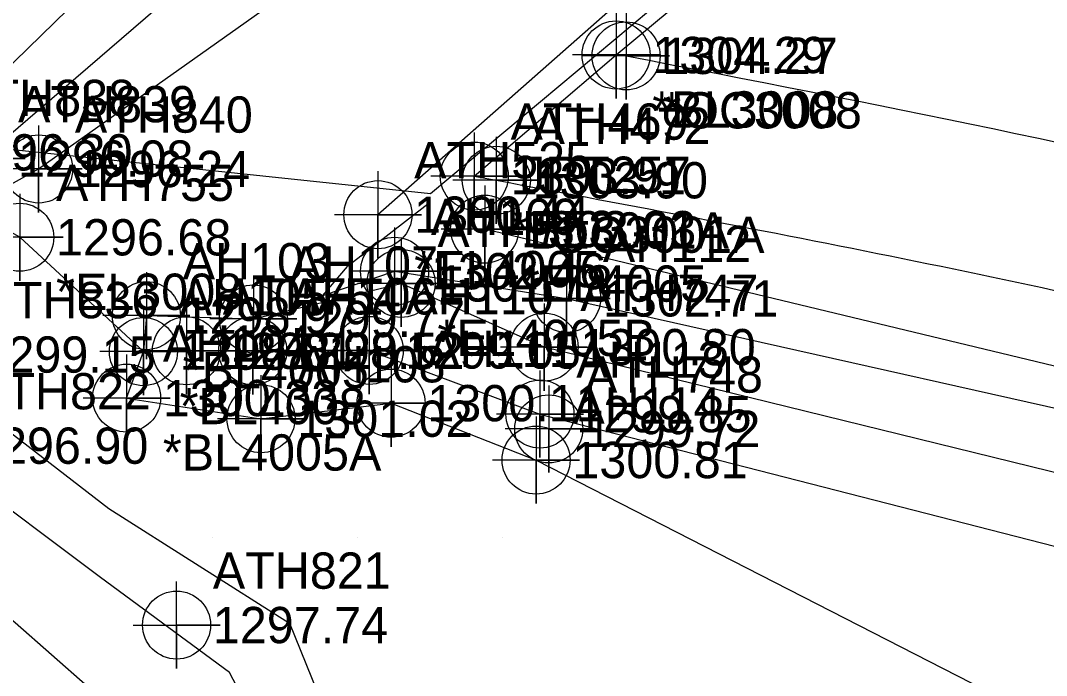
# Model space of a CAD drawing. Extents: x 1234484 to 1235382, y 695050 to 695510.
# Drawn here: x 1234936.8 to 1235007.5, y 695270.5 to 695315.6 of the extents above; entities that cross this region are included whole.
import ezdxf

# ---------------------------------------------------------------- set-up
doc = ezdxf.new("R2010")
doc.units = 0
for name, color, linetype in [('Exist DTM Breakline', 7, 'Continuous'), ('Exist DTM Breakline Cogo Comment', 7, 'Continuous'), ('Exist DTM Breakline Cogo Elevation', 7, 'Continuous'), ('Exist DTM Breakline Cogo Number', 7, 'Continuous'), ('Exist DTM Breakline Cogo Point CELL', 7, 'Continuous'), ('Exist DTM Breakline Underwater', 7, 'Continuous'), ('Exist DTM Crownline', 7, 'Continuous'), ('Exist DTM Crownline Cogo Comment', 7, 'Continuous'), ('Exist DTM Crownline Cogo Elevation', 7, 'Continuous'), ('Exist DTM Crownline Cogo Number', 7, 'Continuous'), ('Exist DTM Crownline Cogo Point CELL', 7, 'Continuous'), ('Exist DTM Drainline Cogo Elevation', 7, 'Continuous'), ('Exist DTM Drainline Cogo Number', 7, 'Continuous'), ('Exist DTM Drainline Cogo Point CELL', 7, 'Continuous'), ('Exist DTM QL2 LIDAR Elevation Point', 7, 'Continuous'), ('Exist DTM Regular Point Cogo Elevation', 7, 'Continuous'), ('Exist DTM Regular Point Cogo Number', 7, 'Continuous'), ('Exist DTM Regular Point Underwater CELL', 7, 'Continuous'), ('Exist DTM Regular Point Underwater Cogo Comment', 7, 'Continuous'), ('Exist DTM Regular Point Underwater Cogo Elevation', 7, 'Continuous'), ('Exist DTM Regular Point Underwater Cogo Number', 7, 'Continuous'), ('Exist Hydro Stream or Body of Water', 7, 'Continuous'), ('Exist Hydro Stream or Body of Water Cogo Elevation', 7, 'Continuous'), ('Exist Hydro Stream or Body of Water Cogo Number', 7, 'Continuous'), ('Exist Hydro Stream or Body of Water Cogo Point CELL', 7, 'Continuous'), ('Exist Roads EOP', 7, 'Continuous'), ('Exist Roads EOP Cogo Comment', 7, 'Continuous'), ('Exist Roads EOP Cogo Elevation', 7, 'Continuous'), ('Exist Roads EOP Cogo Number', 7, 'Continuous'), ('Exist Roads EOP Cogo Point CELL', 7, 'Continuous'), ('Exist Structure Major Deck Tunnel Box Culvert', 7, 'Continuous')]:
    doc.layers.add(name, color=color, linetype=linetype)

msp = doc.modelspace()

# ---------------------------------------------------------------- linework, layer by layer
at = {"layer": 'Exist DTM Breakline'}
for p, q in [((1234990.761, 695328.067), (1234961.429, 695302.218)), ((1234964.862, 695302.939), (1234959.346, 695298.638)), ((1234957.627, 695296.648), (1234959.346, 695298.638))]:
    msp.add_line(p, q, dxfattribs=at)
for points in [[(1235258.778, 695187.05), (1235221.35, 695207.416), (1235173.519, 695232.644), (1235125.211, 695254.804), (1235075.73, 695275.107), (1235023.735, 695288.012), (1234968.789, 695301.22)], [(1234957.627, 695296.648), (1234962.584, 695298.324), (1234974.436, 695296.452), (1235023.384, 695285.46)], [(1234933.683, 695295.436), (1234929.419, 695292.356), (1234942.895, 695281.98), (1234955.338, 695274.07), (1234960.662, 695260.925), (1234955.311, 695244.507), (1234951.042, 695246.761), (1234943.062, 695238.239), (1234919.786, 695222.886), (1234917.573, 695214.076), (1234899.933, 695199.243), (1234885.657, 695179.089)], [(1234882.128, 695182.331), (1234896.107, 695201.799), (1234912.336, 695216.249), (1234916.953, 695226.235), (1234940.483, 695242.348), (1234951.207, 695257.798), (1234946.446, 695265.278), (1234936.421, 695274.091), (1234919.314, 695287.826), (1234914.388, 695289.733)]]:
    msp.add_lwpolyline(points, dxfattribs=at)
at = {"layer": 'Exist DTM Breakline Cogo Point CELL'}
for points in [[(1234961.429, 695305.218), (1234961.429, 695299.218), (1234961.429, 695302.218), (1234964.429, 695302.218), (1234958.429, 695302.218)], [(1234968.789, 695304.22), (1234968.789, 695298.22), (1234968.789, 695301.22), (1234971.789, 695301.22), (1234965.789, 695301.22)], [(1234962.584, 695301.324), (1234962.584, 695295.324), (1234962.584, 695298.324), (1234965.584, 695298.324), (1234959.584, 695298.324)], [(1234963.03, 695300.482), (1234963.03, 695294.482), (1234963.03, 695297.482), (1234966.03, 695297.482), (1234960.03, 695297.482)], [(1234974.436, 695299.452), (1234974.436, 695293.452), (1234974.436, 695296.452), (1234977.436, 695296.452), (1234971.436, 695296.452)], [(1234945.477, 695298.262), (1234945.477, 695292.262), (1234945.477, 695295.262), (1234948.477, 695295.262), (1234942.477, 695295.262)], [(1234952.851, 695298.033), (1234952.851, 695292.033), (1234952.851, 695295.033), (1234955.851, 695295.033), (1234949.851, 695295.033)], [(1234972.886, 695296.093), (1234972.886, 695290.093), (1234972.886, 695293.093), (1234975.886, 695293.093), (1234969.886, 695293.093)], [(1234944.112, 695292.587), (1234944.112, 695286.587), (1234944.112, 695289.587), (1234947.112, 695289.587), (1234941.112, 695289.587)], [(1234962.335, 695292.234), (1234962.335, 695286.234), (1234962.335, 695289.234), (1234965.335, 695289.234), (1234959.335, 695289.234)], [(1234953.373, 695291.163), (1234953.373, 695285.163), (1234953.373, 695288.163), (1234956.373, 695288.163), (1234950.373, 695288.163)], [(1234972.332, 695288.316), (1234972.332, 695282.316), (1234972.332, 695285.316), (1234975.332, 695285.316), (1234969.332, 695285.316)]]:
    msp.add_lwpolyline(points, dxfattribs=at)
for centre in [(1234961.429, 695302.218), (1234968.789, 695301.22), (1234962.584, 695298.324), (1234963.03, 695297.482), (1234974.436, 695296.452), (1234945.477, 695295.262), (1234952.851, 695295.033), (1234972.886, 695293.093), (1234944.112, 695289.587), (1234962.335, 695289.234), (1234953.373, 695288.163), (1234972.332, 695285.316)]:
    msp.add_circle(centre, 2.344, dxfattribs=at)
at = {"layer": 'Exist DTM Breakline Underwater'}
for points in [[(1234766.421, 695209.389), (1234812.885, 695247.237), (1234843.411, 695272.621), (1234869.986, 695279.055), (1234895.378, 695289.036), (1234916.238, 695295.408), (1234934.131, 695306.081), (1234961.466, 695329.617), (1234991.436, 695342.664), (1235009.265, 695346.147), (1235040.352, 695365.623), (1235072.367, 695380.008), (1235092.174, 695396.335)], [(1234948.239, 695292.841), (1234952.805, 695292.84), (1234960.83, 695292.864), (1234972.599, 695288.481), (1235023.203, 695275.502), (1235056.399, 695264.585), (1235086.587, 695258.395), (1235121.582, 695234.941), (1235168.445, 695213.485), (1235191.313, 695204.186), (1235209.05, 695188.429), (1235246.922, 695166.749), (1235265.478, 695149.496)]]:
    msp.add_lwpolyline(points, dxfattribs=at)
at = {"layer": 'Exist DTM Crownline'}
msp.add_line((1234977.842, 695313.219), (1234978.534, 695313.159), dxfattribs=at)
msp.add_spline([(1234978.534, 695313.159), (1235028.867, 695302.317), (1235079.475, 695286.154), (1235130.202, 695265.942), (1235178.94, 695242.599), (1235226.8, 695217.474)], degree=3, dxfattribs=at)
at = {"layer": 'Exist DTM Crownline Cogo Point CELL'}
for points in [[(1234977.842, 695316.219), (1234977.842, 695310.219), (1234977.842, 695313.219), (1234980.842, 695313.219), (1234974.842, 695313.219)], [(1234978.534, 695316.159), (1234978.534, 695310.159), (1234978.534, 695313.159), (1234981.534, 695313.159), (1234975.534, 695313.159)], [(1234936.748, 695303.66), (1234936.748, 695297.66), (1234936.748, 695300.66), (1234939.748, 695300.66), (1234933.748, 695300.66)]]:
    msp.add_lwpolyline(points, dxfattribs=at)
for centre in [(1234977.842, 695313.219), (1234978.534, 695313.159), (1234936.748, 695300.66)]:
    msp.add_circle(centre, 2.344, dxfattribs=at)
at = {"layer": 'Exist DTM Drainline Cogo Point CELL'}
msp.add_lwpolyline([(1234938.044, 695308.366), (1234938.044, 695302.366), (1234938.044, 695305.366), (1234941.044, 695305.366), (1234935.044, 695305.366)], dxfattribs=at)
msp.add_circle((1234938.044, 695305.366), 2.344, dxfattribs=at)
at = {"layer": 'Exist DTM QL2 LIDAR Elevation Point'}
for p, q in [((1234950, 695280), (1234950, 695280)), ((1234960, 695280), (1234960, 695280)), ((1234970, 695280), (1234970, 695280))]:
    msp.add_line(p, q, dxfattribs=at)
at = {"layer": 'Exist DTM Regular Point Underwater CELL'}
for points in [[(1234934.131, 695309.081), (1234934.131, 695303.081), (1234934.131, 695306.081), (1234937.131, 695306.081), (1234931.131, 695306.081)], [(1234945.266, 695295.782), (1234945.266, 695289.782), (1234945.266, 695292.782), (1234948.266, 695292.782), (1234942.266, 695292.782)], [(1234948.239, 695295.841), (1234948.239, 695289.841), (1234948.239, 695292.841), (1234951.239, 695292.841), (1234945.239, 695292.841)], [(1234952.805, 695295.84), (1234952.805, 695289.84), (1234952.805, 695292.84), (1234955.805, 695292.84), (1234949.805, 695292.84)], [(1234960.83, 695295.864), (1234960.83, 695289.864), (1234960.83, 695292.864), (1234963.83, 695292.864), (1234957.83, 695292.864)], [(1234972.599, 695291.481), (1234972.599, 695285.481), (1234972.599, 695288.481), (1234975.599, 695288.481), (1234969.599, 695288.481)], [(1234973.204, 695290.456), (1234973.204, 695284.456), (1234973.204, 695287.456), (1234976.204, 695287.456), (1234970.204, 695287.456)]]:
    msp.add_lwpolyline(points, dxfattribs=at)
for centre in [(1234945.266, 695292.782), (1234948.239, 695292.841), (1234952.805, 695292.84), (1234960.83, 695292.864), (1234972.599, 695288.481), (1234973.204, 695287.456)]:
    msp.add_circle(centre, 2.344, dxfattribs=at)
at = {"layer": 'Exist Hydro Stream or Body of Water'}
for p, q in [((1234933.154, 695302.663), (1234938.044, 695305.366)), ((1234952.851, 695295.033), (1234963.03, 695297.482)), ((1234945.477, 695295.262), (1234945.266, 695292.782))]:
    msp.add_line(p, q, dxfattribs=at)
for points in [[(1234766.439, 695214.543), (1234809.451, 695250.146), (1234840.783, 695273.683), (1234870.231, 695281.467), (1234894.384, 695292.767), (1234915.014, 695298.345), (1234929.933, 695306.511), (1234953.845, 695329.807), (1234986.204, 695341.472), (1235008.526, 695348.915), (1235037.336, 695368.653), (1235069.491, 695383.302), (1235088.448, 695400.861)], [(1234938.044, 695305.366), (1234971.304, 695328.94), (1234992.169, 695338.626), (1235010.649, 695342.979), (1235043.523, 695362.073), (1235076.562, 695377.561), (1235094.01, 695394.044)], [(1234944.112, 695289.587), (1234945.266, 695292.782), (1234936.748, 695300.66), (1234933.154, 695302.663)], [(1235024.437, 695280.431), (1234972.886, 695293.093), (1234963.03, 695297.482)], [(1234945.477, 695295.262), (1234952.851, 695295.033)], [(1234884.024, 695180.655), (1234897.944, 695200.742), (1234915.887, 695215.628), (1234918.027, 695224.801), (1234941.893, 695240.452), (1234957.27, 695259.086), (1234951.207, 695270.685), (1234942.31, 695277.234), (1234922.587, 695292.008)], [(1234944.112, 695289.587), (1234953.373, 695288.163), (1234962.335, 695289.234), (1234972.332, 695285.316), (1235018.754, 695261.568)]]:
    msp.add_lwpolyline(points, dxfattribs=at)
at = {"layer": 'Exist Hydro Stream or Body of Water Cogo Point CELL'}
msp.add_lwpolyline([(1234944.554, 695273.948), (1234950.554, 695273.948), (1234947.554, 695273.948), (1234947.554, 695270.948), (1234947.554, 695276.948)], dxfattribs=at)
msp.add_circle((1234947.554, 695273.948), 2.344, dxfattribs=at)
at = {"layer": 'Exist Roads EOP'}
msp.add_line((1234968.075, 695304.88), (1234969.592, 695304.589), dxfattribs=at)
msp.add_lwpolyline([(1234968.075, 695304.88), (1234977.842, 695313.219), (1234987.73, 695321.443)], dxfattribs=at)
for points in [[(1234989.744, 695321.275), (1235032.632, 695310.758), (1235082.97, 695294.625), (1235134.247, 695274.482), (1235183.928, 695250.955), (1235232.115, 695225.68)], [(1234969.592, 695304.589), (1235025.451, 695292.964), (1235076.313, 695277.193), (1235126.218, 695256.569), (1235174.523, 695234.324), (1235222.247, 695208.988)]]:
    msp.add_spline(points, degree=3, dxfattribs=at)
at = {"layer": 'Exist Roads EOP Cogo Point CELL'}
for points in [[(1234968.075, 695307.88), (1234968.075, 695301.88), (1234968.075, 695304.88), (1234971.075, 695304.88), (1234965.075, 695304.88)], [(1234969.592, 695307.589), (1234969.592, 695301.589), (1234969.592, 695304.589), (1234972.592, 695304.589), (1234966.592, 695304.589)]]:
    msp.add_lwpolyline(points, dxfattribs=at)
for centre in [(1234968.075, 695304.88), (1234969.592, 695304.589)]:
    msp.add_circle(centre, 2.344, dxfattribs=at)
at = {"layer": 'Exist Structure Major Deck Tunnel Box Culvert'}
msp.add_lwpolyline([(1234932.242, 695330.836), (1234906.381, 695309.848), (1234965.045, 695303.686), (1234990.33, 695324.837), (1234932.242, 695330.836)], dxfattribs=at)

# ---------------------------------------------------------------- texts
at = {"layer": 'Exist DTM Breakline Cogo Comment'}
for s, p in [('*EL4005', (1234963.929, 695297.218)), ('*EL4005', (1234971.289, 695296.22)), ('*EL4005B', (1234965.53, 695292.482)), ('*BL4005', (1234947.977, 695290.262)), ('*BL4005A', (1234946.612, 695284.587))]:
    msp.add_text(s, height=2.5, dxfattribs=at).set_placement(p)
at = {"layer": 'Exist DTM Breakline Cogo Elevation'}
for s, p in [('1300.44', (1234963.929, 695300.968)), ('1303.33', (1234971.289, 695299.97)), ('1302.46', (1234965.084, 695297.074)), ('1301.78', (1234965.53, 695296.232)), ('1302.71', (1234976.936, 695295.202)), ('1298.97', (1234947.977, 695294.012)), ('1299.77', (1234955.351, 695293.783)), ('1300.80', (1234975.386, 695291.843)), ('1300.33', (1234946.612, 695288.337)), ('1300.11', (1234964.835, 695287.984)), ('1301.02', (1234955.873, 695286.913)), ('1300.81', (1234974.832, 695284.066))]:
    msp.add_text(s, height=2.5, dxfattribs=at).set_placement(p)
at = {"layer": 'Exist DTM Breakline Cogo Number'}
for s, p in [('ATH525', (1234963.929, 695304.718)), ('JRT257', (1234971.289, 695303.72)), ('AH109', (1234965.084, 695300.824)), ('ATH753', (1234965.53, 695299.982)), ('AH112', (1234976.936, 695298.952)), ('AH103', (1234947.977, 695297.762)), ('AH107', (1234955.351, 695297.533)), ('ATH747', (1234975.386, 695295.593)), ('AH104', (1234946.612, 695292.087)), ('AH111', (1234964.835, 695291.734)), ('AH108', (1234955.873, 695290.663)), ('AH114', (1234974.832, 695287.816))]:
    msp.add_text(s, height=2.5, dxfattribs=at).set_placement(p)
at = {"layer": 'Exist DTM Crownline Cogo Comment'}
for s, p in [('*BL3008', (1234980.342, 695308.219)), ('*OC3008', (1234981.034, 695308.159)), ('*EL3008', (1234939.248, 695295.66))]:
    msp.add_text(s, height=2.5, dxfattribs=at).set_placement(p)
at = {"layer": 'Exist DTM Crownline Cogo Elevation'}
for s, p in [('1304.29', (1234980.342, 695311.969)), ('1304.27', (1234981.034, 695311.909)), ('1296.68', (1234939.248, 695299.41))]:
    msp.add_text(s, height=2.5, dxfattribs=at).set_placement(p)
at = {"layer": 'Exist DTM Crownline Cogo Number'}
msp.add_text('ATH755', height=2.5, dxfattribs=at).set_placement((1234939.248, 695303.16))
at = {"layer": 'Exist DTM Drainline Cogo Elevation'}
for s, p in [('1296.30', (1234932.433, 695305.261)), ('1296.24', (1234940.544, 695304.116))]:
    msp.add_text(s, height=2.5, dxfattribs=at).set_placement(p)
at = {"layer": 'Exist DTM Drainline Cogo Number'}
for s, p in [('ATH838', (1234932.433, 695309.011)), ('ATH840', (1234940.544, 695307.866))]:
    msp.add_text(s, height=2.5, dxfattribs=at).set_placement(p)
at = {"layer": 'Exist DTM Regular Point Cogo Elevation'}
msp.add_text('1299.15', height=2.5, dxfattribs=at).set_placement((1234934.035, 695291.334))
at = {"layer": 'Exist DTM Regular Point Cogo Number'}
msp.add_text('ATH836', height=2.5, dxfattribs=at).set_placement((1234934.035, 695295.084))
at = {"layer": 'Exist DTM Regular Point Underwater Cogo Comment'}
msp.add_text('*BL4008', height=2.5, dxfattribs=at).set_placement((1234947.766, 695287.782))
at = {"layer": 'Exist DTM Regular Point Underwater Cogo Elevation'}
for s, p in [('1296.08', (1234936.631, 695304.831)), ('1298.01', (1234947.766, 695291.532)), ('1298.29', (1234950.739, 695291.591)), ('1298.52', (1234955.305, 695291.59)), ('1299.05', (1234963.33, 695291.614)), ('1299.85', (1234975.099, 695287.231)), ('1299.72', (1234975.704, 695286.206))]:
    msp.add_text(s, height=2.5, dxfattribs=at).set_placement(p)
at = {"layer": 'Exist DTM Regular Point Underwater Cogo Number'}
for s, p in [('ATH839', (1234936.631, 695308.581)), ('AH105', (1234947.766, 695295.282)), ('ATH754', (1234950.739, 695295.341)), ('AH106', (1234955.305, 695295.34)), ('AH110', (1234963.33, 695295.364)), ('AH113', (1234975.099, 695290.981)), ('ATH748', (1234975.704, 695289.956))]:
    msp.add_text(s, height=2.5, dxfattribs=at).set_placement(p)
at = {"layer": 'Exist Hydro Stream or Body of Water Cogo Elevation'}
for s, p in [('1296.90', (1234933.524, 695285.055)), ('1297.74', (1234950.054, 695272.698))]:
    msp.add_text(s, height=2.5, dxfattribs=at).set_placement(p)
at = {"layer": 'Exist Hydro Stream or Body of Water Cogo Number'}
for s, p in [('ATH822', (1234933.524, 695288.805)), ('ATH821', (1234950.054, 695276.448))]:
    msp.add_text(s, height=2.5, dxfattribs=at).set_placement(p)
at = {"layer": 'Exist Roads EOP Cogo Comment'}
for s, p in [('*BL3001A', (1234970.575, 695299.88)), ('*OC3001A', (1234972.092, 695299.589))]:
    msp.add_text(s, height=2.5, dxfattribs=at).set_placement(p)
at = {"layer": 'Exist Roads EOP Cogo Elevation'}
for s, p in [('1303.91', (1234970.575, 695303.63)), ('1303.90', (1234972.092, 695303.339))]:
    msp.add_text(s, height=2.5, dxfattribs=at).set_placement(p)
at = {"layer": 'Exist Roads EOP Cogo Number'}
for s, p in [('ATH469', (1234970.575, 695307.38)), ('ATH472', (1234972.092, 695307.089))]:
    msp.add_text(s, height=2.5, dxfattribs=at).set_placement(p)

doc.saveas('drawing.dxf')
